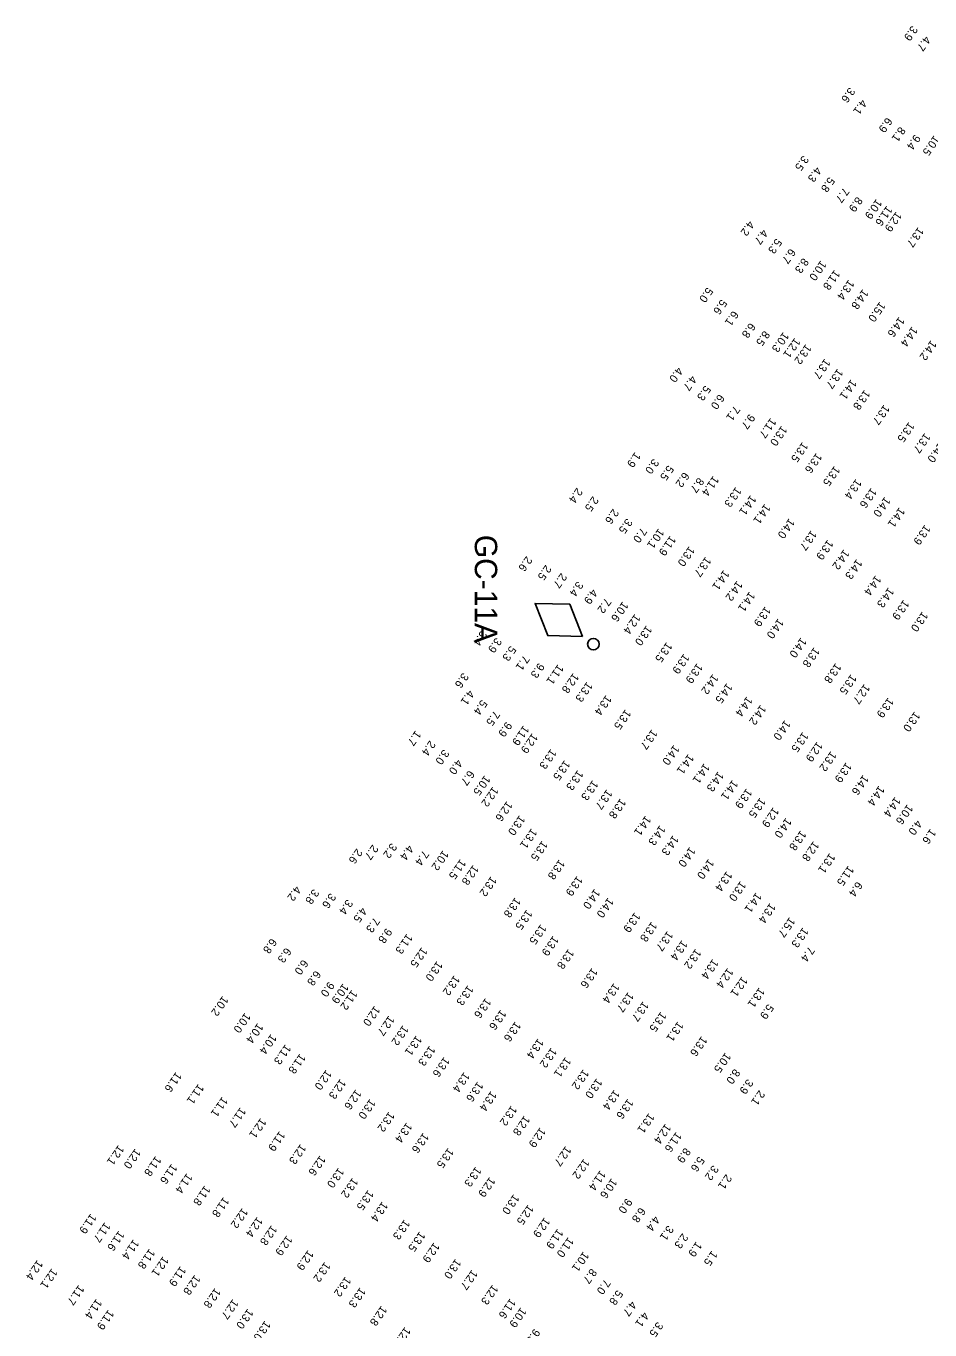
# Model space of a CAD drawing. Extents: x 815385 to 820851, y 582449 to 604245.
# Drawn here: x 819015 to 819579, y 587763 to 588578 of the extents above; entities that cross this region are included whole.
import ezdxf

# ---------------------------------------------------------------- set-up
doc = ezdxf.new("R2010")
doc.units = 0
for name, color, linetype in [('V-CHAN-AIDS', 7, 'Continuous'), ('V-TOPO-SOUN-021309', 7, 'Continuous'), ('V-TOPO-SOUN-021509', 7, 'Continuous')]:
    doc.layers.add(name, color=color, linetype=linetype)

msp = doc.modelspace()

# ---------------------------------------------------------------- linework, layer by layer
at = {"layer": 'V-CHAN-AIDS'}
msp.add_lwpolyline([(819361.92, 588196.62), (819354.06, 588216.77), (819332.43, 588217.27), (819340.29, 588197.11)], close=True, dxfattribs=at)
msp.add_circle((819368.8, 588191.8), 3.6, dxfattribs=at)

# ---------------------------------------------------------------- texts
msp.add_text('GC-11A', height=14, rotation=270, dxfattribs=at).set_placement((819294.75, 588260.14))
at = {"layer": 'V-TOPO-SOUN-021309'}
for s, p in [('3.9', (819567.79, 588578.69)), ('4.7', (819575.93, 588572.26)), ('3.6', (819528.67, 588540.09)), ('4.1', (819536.16, 588532.62)), ('6.9', (819551.95, 588521.37)), ('8.1', (819560.17, 588515.54)), ('9.4', (819569.54, 588510.69)), ('10.5 ', (819581.56, 588510.07)), ('3.5', (819499.73, 588497.52)), ('4.3', (819507.75, 588490.49)), ('5.8', (819515.97, 588484.11)), ('7.7', (819525.07, 588477.49)), ('8.9', (819533.35, 588471.78)), ('10.9 ', (819545.52, 588470.33)), ('11.6 ', (819552.03, 588466.09)), ('12.9 ', (819557.92, 588462.43)), ('13.7 ', (819571.67, 588452.74))]:
    msp.add_text(s, height=5, rotation=234.911, dxfattribs=at).set_placement(p)
at = {"layer": 'V-TOPO-SOUN-021509'}
for s, p in [('4.2', (819465.79, 588456.81)), ('4.7', (819474.34, 588451.44)), ('5.3', (819482.97, 588445.68)), ('6.7', (819491.59, 588439.43)), ('8.3', (819499.69, 588433.49)), ('10.0 ', (819510.81, 588431.87)), ('11.8 ', (819519.39, 588426.03)), ('13.4 ', (819528.23, 588419.86)), ('5.0', (819439.93, 588415.2)), ('14.8 ', (819537.07, 588413.98)), ('5.6', (819448.72, 588407.67)), ('6.1', (819455.93, 588400.52)), ('15.0 ', (819547.66, 588406.1)), ('6.8', (819466.54, 588392.98)), ('14.6 ', (819559.7, 588396.64)), ('8.5', (819475.44, 588388.05)), ('10.3 ', (819487.41, 588387.17)), ('14.4 ', (819567.82, 588390.61)), ('12.1 ', (819494.56, 588383.52)), ('13.2 ', (819501.48, 588379.61)), ('14.2 ', (819579.65, 588382.04)), ('13.7 ', (819513.29, 588370.52)), ('4.0', (819421.21, 588365.31)), ('4.7', (819429.87, 588360.05)), ('13.7 ', (819521.31, 588364.3)), ('5.3', (819438.57, 588353.83)), ('14.1 ', (819529.72, 588357.61)), ('13.8 ', (819538.16, 588351.08)), ('6.0', (819447.16, 588348.4)), ('7.1', (819456.81, 588341.18)), ('9.7', (819466.2, 588336.01)), ('13.7 ', (819550.31, 588341.75)), ('11.7 ', (819479.51, 588333.48)), ('13.0 ', (819486.34, 588328.58)), ('13.5 ', (819565.83, 588330.92)), ('13.5 ', (819499.4, 588318.43)), ('13.7 ', (819575.79, 588324.05)), ('1.9', (819394.8, 588312.1)), ('13.6 ', (819508.05, 588311.59)), ('14.0 ', (819584.6, 588318.19)), ('3.0', (819406.17, 588308.05)), ('5.5', (819415.43, 588303.97)), ('13.5 ', (819519.33, 588303.5)), ('6.2', (819425.19, 588299.69)), ('8.7', (819434.34, 588296.28)), ('11.4 ', (819443.7, 588297.29)), ('13.4 ', (819532.8, 588295.35)), ('2.4', (819358.51, 588289.83)), ('13.3 ', (819457.74, 588290.32)), ('13.6 ', (819542.3, 588289.75)), ('2.5', (819368.48, 588284.58)), ('14.1 ', (819467, 588285.27)), ('14.1 ', (819475.88, 588279.8)), ('14.0 ', (819550.82, 588284.2)), ('2.6', (819381.14, 588276.77)), ('3.5', (819389.62, 588270.75)), ('14.0 ', (819491.09, 588270.7)), ('14.1 ', (819559.87, 588277.6)), ('7.0', (819398.65, 588265)), ('10.1 ', (819409.51, 588264.41)), ('13.7 ', (819504.81, 588263.24)), ('13.9 ', (819575.84, 588266.7)), ('11.9 ', (819416.83, 588259.92)), ('13.0 ', (819428.6, 588253.28)), ('13.9 ', (819515.12, 588257.36)), ('2.6', (819327.03, 588247.14)), ('13.7 ', (819438.88, 588246.74)), ('14.2 ', (819525.2, 588251.28)), ('14.3 ', (819533.24, 588245.27)), ('2.5', (819339.04, 588241.64)), ('14.1 ', (819450.19, 588238.47)), ('2.7', (819348.73, 588236.63)), ('3.4', (819358.89, 588231.47)), ('14.2 ', (819458.49, 588231.68)), ('14.4 ', (819545.06, 588235.11)), ('4.9', (819367.92, 588226.64)), ('14.1 ', (819466.31, 588224.95)), ('14.3 ', (819553.08, 588227.54)), ('7.2', (819376.35, 588220.97)), ('10.6 ', (819387.1, 588218.77)), ('13.9 ', (819476.12, 588215.66)), ('13.9 ', (819562.54, 588219.81)), ('13.0 ', (819574.27, 588212.48)), ('12.4 ', (819394.72, 588210.96)), ('14.0 ', (819484.21, 588208.15)), ('3.4', (819298.8, 588200.58)), ('13.0 ', (819401.92, 588203.78)), ('14.0 ', (819498.43, 588196.22)), ('3.9', (819307.99, 588196.24)), ('5.3', (819317.01, 588191.1)), ('13.5 ', (819414.54, 588193.36)), ('13.8 ', (819506.65, 588190.17)), ('7.1', (819325.33, 588185.17)), ('9.3', (819334.65, 588180.45)), ('13.9 ', (819425.28, 588186.11)), ('13.9 ', (819433.57, 588180.17)), ('13.8 ', (819520.11, 588180.25)), ('3.6', (819287.33, 588174.26)), ('11.1 ', (819346.68, 588179.49)), ('12.8 ', (819356.24, 588174.07)), ('14.2 ', (819443.37, 588173.4)), ('13.5 ', (819529.68, 588173.26)), ('13.3 ', (819364.77, 588168.57)), ('14.5 ', (819452.14, 588167.75)), ('12.7 ', (819538.03, 588167.23)), ('4.1', (819290.94, 588163.56)), ('5.4', (819299, 588157.42)), ('13.4 ', (819376.68, 588160.23)), ('14.4 ', (819464.68, 588159.45)), ('13.9 ', (819552.89, 588158.71)), ('7.5', (819306.87, 588150.62)), ('13.5 ', (819388.79, 588151.35)), ('14.2 ', (819473.2, 588154.19)), ('13.0 ', (819569.41, 588149.98)), ('9.9', (819314.4, 588143.68)), ('11.9 ', (819325.19, 588141.35)), ('14.0 ', (819488.4, 588144.67)), ('1.7', (819257.74, 588138.13)), ('2.4', (819266.66, 588131.93)), ('12.9 ', (819330.62, 588136.45)), ('13.7 ', (819405.28, 588138.86)), ('13.5 ', (819499.57, 588137.21)), ('12.9 ', (819508.57, 588131.17)), ('3.0', (819275.19, 588126.37)), ('13.3 ', (819342.23, 588126.61)), ('14.0 ', (819419.06, 588129.13)), ('14.1 ', (819428.07, 588123.44)), ('13.2 ', (819517.11, 588125.19)), ('4.0', (819283.56, 588120.19)), ('13.5 ', (819350.78, 588119.59)), ('14.1 ', (819437.99, 588117.58)), ('13.9 ', (819526.66, 588118.17)), ('6.7', (819291.02, 588113.31)), ('10.5 ', (819300.91, 588110.14)), ('13.3 ', (819358.99, 588113.35)), ('13.3 ', (819368.31, 588107.05)), ('14.3 ', (819446.71, 588112.53)), ('14.1 ', (819455.66, 588107.29)), ('14.6 ', (819537.31, 588110.44)), ('12.2 ', (819306, 588103.05)), ('13.7 ', (819377.13, 588101.35)), ('13.9 ', (819464.41, 588101.9)), ('14.4 ', (819547.17, 588103.66)), ('12.6 ', (819314.78, 588093.99)), ('13.8 ', (819385.63, 588095.65)), ('13.5 ', (819472.91, 588096.18)), ('14.4 ', (819557.21, 588096.67)), ('10.6 ', (819564.9, 588092)), ('13.0 ', (819322.65, 588085.18)), ('14.1 ', (819401.37, 588084.96)), ('12.9 ', (819481.18, 588090.16)), ('14.0 ', (819489.08, 588083.55)), ('13.1 ', (819330.14, 588076.95)), ('14.3 ', (819410.29, 588078.91)), ('13.8 ', (819498.23, 588075.7)), ('4.0', (819570.59, 588082.31)), ('1.6', (819579.3, 588076.75)), ('2.7', (819230.9, 588066.84)), ('3.2', (819242.56, 588067.87)), ('4.4', (819253.07, 588066.66)), ('13.5 ', (819336.81, 588069.28)), ('14.3 ', (819418.56, 588072.65)), ('12.8 ', (819506.29, 588068.99)), ('2.6', (819221, 588064.4)), ('7.4', (819262.51, 588063.28)), ('10.2 ', (819274.88, 588063.26)), ('11.5 ', (819285.68, 588057.74)), ('14.0 ', (819429.01, 588065.4)), ('14.0 ', (819440.72, 588057.87)), ('13.1 ', (819516.36, 588061.47)), ('12.8 ', (819293.73, 588054.12)), ('13.8 ', (819347.48, 588057.55)), ('13.4 ', (819452.04, 588050.2)), ('11.5 ', (819528.03, 588053.65)), ('13.2 ', (819304.88, 588047.01)), ('13.9 ', (819358.66, 588047.29)), ('13.0 ', (819460.64, 588044.02)), ('6.4', (819533.37, 588043.83)), ('4.2', (819182.71, 588041.12)), ('3.8', (819193.94, 588039.16)), ('3.6', (819204.46, 588036.57)), ('13.8 ', (819319.95, 588033.81)), ('14.0 ', (819369.52, 588039.16)), ('14.0 ', (819377.99, 588033.71)), ('14.1 ', (819470.4, 588036.89)), ('3.4', (819215.03, 588032.67)), ('4.5', (819223.9, 588027.73)), ('13.5 ', (819327.16, 588026.2)), ('13.4 ', (819479.13, 588030.32)), ('7.3', (819231.84, 588021.4)), ('13.5 ', (819335.94, 588017.05)), ('13.9 ', (819394.63, 588024.51)), ('13.8 ', (819405.13, 588018.67)), ('15.7 ', (819491.31, 588021.46)), ('9.8', (819239.49, 588014.71)), ('11.3 ', (819252.35, 588011.13)), ('13.9 ', (819343.67, 588009.85)), ('13.7 ', (819415.07, 588012.82)), ('13.3 ', (819499.66, 588015.07)), ('6.8', (819167.54, 588008.3)), ('6.3', (819176.62, 588002.51)), ('12.5 ', (819261.61, 588002.7)), ('13.8 ', (819353.21, 588001.62)), ('13.4 ', (819424.09, 588007.07)), ('13.2 ', (819432.64, 588001.74)), ('7.4', (819503.44, 588003.17)), ('6.0', (819187.19, 587995.04)), ('13.0 ', (819271.13, 587994.04)), ('13.4 ', (819443.36, 587995.35)), ('6.8', (819195.06, 587988.19)), ('13.2 ', (819281.91, 587985.14)), ('13.6 ', (819367.95, 587989.74)), ('12.4 ', (819452.68, 587989.76)), ('12.1 ', (819461.58, 587984.33)), ('9.0', (819203.51, 587981.22)), ('10.9 ', (819212.4, 587980.04)), ('13.3 ', (819290.39, 587978.89)), ('13.4 ', (819381.62, 587980.27)), ('13.1 ', (819472.36, 587977.52)), ('10.2 ', (819137.29, 587972.28)), ('11.2 ', (819217.93, 587976.05)), ('13.6 ', (819301.46, 587970.94)), ('13.7 ', (819390.53, 587974.66)), ('13.7 ', (819399.85, 587968.9)), ('10.0 ', (819151.2, 587961.74)), ('12.0 ', (819232.11, 587966.03)), ('12.7 ', (819241.03, 587959.97)), ('13.6 ', (819310.88, 587963.62)), ('13.5 ', (819410.92, 587962.36)), ('5.9', (819477.86, 587967.26)), ('10.4 ', (819159.12, 587955.25)), ('13.2 ', (819249.84, 587953.91)), ('13.6 ', (819320.02, 587956.28)), ('13.1 ', (819421.58, 587956.32)), ('10.4 ', (819167.44, 587948.42)), ('13.1 ', (819258.18, 587947.53)), ('13.4 ', (819334.24, 587945.66)), ('13.6 ', (819436.39, 587947.13)), ('11.3 ', (819176.44, 587941.99)), ('11.8 ', (819185.52, 587936.2)), ('13.3 ', (819266.53, 587941.12)), ('13.2 ', (819342.49, 587939.95)), ('10.5 ', (819451.23, 587936.88)), ('13.6 ', (819275.56, 587934.14)), ('13.1 ', (819351.35, 587934.01)), ('11.6 ', (819108.16, 587924.77)), ('12.0 ', (819201.87, 587926.08)), ('12.3 ', (819210.72, 587920.4)), ('13.4 ', (819288.05, 587924.63)), ('13.2 ', (819362.5, 587926.37)), ('13.0 ', (819370.83, 587920.75)), ('8.0', (819456.87, 587926.74)), ('3.9', (819465.07, 587920.43)), ('11.1 ', (819122.06, 587917.23)), ('12.6 ', (819220.39, 587913.79)), ('13.6 ', (819296.52, 587918.7)), ('13.4 ', (819304.87, 587912.81)), ('13.4 ', (819381.81, 587913.58)), ('2.1', (819472.39, 587913.41)), ('11.1 ', (819137, 587909.21)), ('13.0 ', (819229.23, 587907.87)), ('13.2 ', (819317.54, 587903.7)), ('13.6 ', (819390.3, 587908)), ('11.7 ', (819148.28, 587902.62)), ('12.1 ', (819161, 587895.93)), ('13.2 ', (819241.13, 587899.93)), ('12.8 ', (819325.69, 587897.48)), ('13.1 ', (819403.45, 587899.02)), ('11.9 ', (819172.8, 587887.79)), ('13.4 ', (819252.13, 587893.12)), ('13.6 ', (819262.54, 587886.71)), ('12.9 ', (819335.53, 587890.08)), ('12.4 ', (819413.82, 587892.42)), ('11.6 ', (819420.5, 587887.24)), ('12.1 ', (819072.18, 587879.06)), ('12.3 ', (819185.89, 587879.7)), ('12.7 ', (819351.47, 587878.45)), ('12.0 ', (819082.61, 587876.84)), ('11.8 ', (819095.41, 587872.18)), ('12.6 ', (819198.03, 587872.54)), ('13.5 ', (819278.08, 587877.25)), ('12.2 ', (819362.86, 587870.51)), ('8.9', (819425.98, 587877.43)), ('5.6', (819434.66, 587871.94)), ('11.6 ', (819105.38, 587867.35)), ('13.0 ', (819209.6, 587864.9)), ('13.3 ', (819295.32, 587865.56)), ('11.4 ', (819373.08, 587863.25)), ('3.2', (819443.47, 587866.55)), ('11.4 ', (819114.89, 587861.45)), ('13.2 ', (819218.38, 587858.65)), ('12.9 ', (819304.01, 587859.1)), ('10.6 ', (819380.15, 587858.28)), ('2.1', (819451.71, 587860.88)), ('11.8 ', (819126.07, 587853.78)), ('11.8 ', (819137.82, 587846.56)), ('13.5 ', (819228.05, 587850.93)), ('13.0 ', (819319.01, 587848.32)), ('12.2 ', (819149.53, 587839.7)), ('13.4 ', (819236.95, 587843.76)), ('12.5 ', (819328.06, 587841.81)), ('9.0', (819389.49, 587845.87)), ('6.8', (819397.87, 587840.18)), ('11.9 ', (819054.89, 587836.23)), ('11.7 ', (819063.67, 587830.82)), ('12.4 ', (819158.85, 587834.15)), ('13.3 ', (819250.75, 587832.53)), ('12.9 ', (819338.24, 587833.82)), ('4.4', (819406.8, 587834.85)), ('11.6 ', (819072.38, 587825.5)), ('12.8 ', (819167.76, 587828.96)), ('12.9 ', (819177.29, 587822.55)), ('13.5 ', (819260.28, 587825.03)), ('11.9 ', (819346.46, 587826.76)), ('11.0 ', (819353.06, 587821.48)), ('3.1', (819415.36, 587828.9)), ('2.3', (819424.43, 587823.94)), ('11.4 ', (819081.54, 587820.13)), ('11.8 ', (819091.49, 587814.24)), ('12.9 ', (819190.56, 587813.39)), ('12.9 ', (819269.23, 587818.17)), ('1.9', (819433.06, 587818.72)), ('12.4 ', (819021.51, 587807.23)), ('12.1 ', (819100.03, 587809.5)), ('13.2 ', (819201.05, 587806.03)), ('13.0 ', (819282.73, 587808.01)), ('10.1 ', (819362.54, 587812.51)), ('1.5', (819442.79, 587813.1)), ('12.1 ', (819030.56, 587801.98)), ('11.9 ', (819110.86, 587803.33)), ('12.8 ', (819119.82, 587797.92)), ('12.7 ', (819292.95, 587801.14)), ('8.7', (819367.38, 587801.95)), ('11.7 ', (819047.32, 587791.61)), ('12.8 ', (819132.52, 587789.75)), ('13.2 ', (819213.91, 587796.84)), ('13.3 ', (819223.09, 587790.09)), ('12.3 ', (819305.85, 587791.83)), ('7.0', (819375.93, 587795.24)), ('11.4 ', (819058.39, 587782.96)), ('12.7 ', (819143.58, 587782.76)), ('11.6 ', (819316.85, 587783.21)), ('5.8', (819383.71, 587788.57)), ('4.7', (819392.24, 587781.63)), ('11.9 ', (819065.87, 587776.17)), ('13.0 ', (819152.89, 587776.76)), ('12.8 ', (819236.39, 587778.64)), ('10.9 ', (819323.46, 587777.57)), ('4.1', (819399.97, 587774.85)), ('13.0 ', (819163.67, 587769.28)), ('12.9 ', (819251.12, 587765.37)), ('3.5', (819408.79, 587768.65)), ('9.3', (819331.93, 587764.32))]:
    msp.add_text(s, height=5, rotation=234.911, dxfattribs=at).set_placement(p)

doc.saveas('drawing.dxf')
